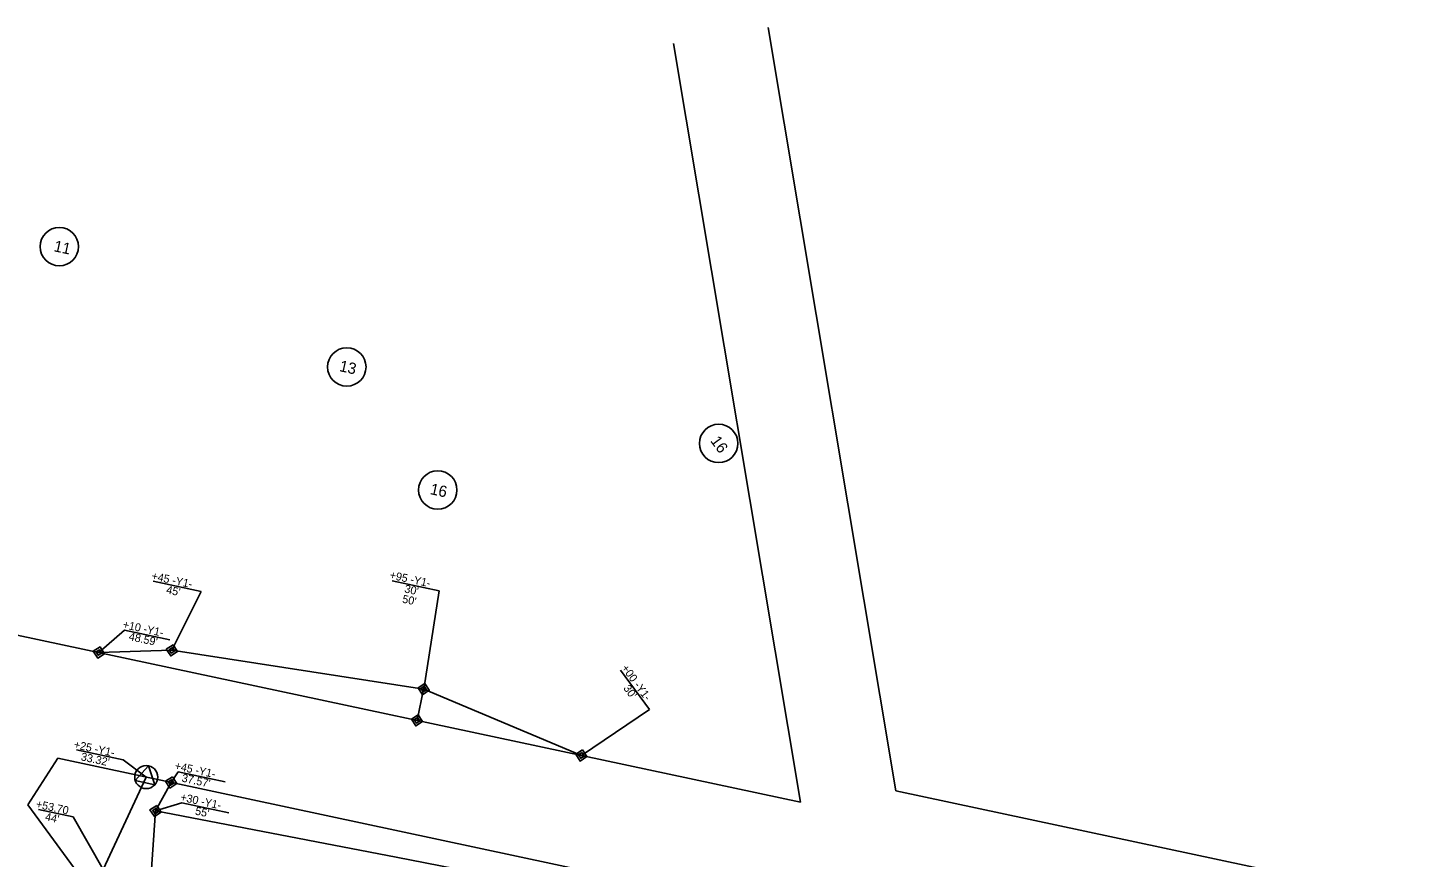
# Model space of a CAD drawing. Extents: x 1762160 to 1765875, y 710174 to 712931.
# Drawn here: x 1763351 to 1764211, y 712412 to 712931 of the extents above; entities that cross this region are included whole.
import ezdxf

# ---------------------------------------------------------------- set-up
doc = ezdxf.new("R2010")
doc.units = 0
for name, color, linetype in [('Exist Building Foundations', 7, 'Continuous'), ('Exist Other Culture Area Outline', 7, 'Continuous'), ('Exist Other Culture Fence Line', 7, 'Continuous'), ('Exist Other Culture Sign CELL', 7, 'Continuous'), ('Exist Roads Curbs', 7, 'Continuous'), ('Exist Roads EOP Other', 7, 'Continuous'), ('Exist Roads Soil', 7, 'Continuous'), ('Exist Structure Minor Head and End Wall', 7, 'Continuous'), ('Exist Utilities Other Pole CELL', 7, 'Continuous'), ('Exist Utilities Other Pole With Base CELL', 7, 'Continuous'), ('Exist Vegetation Tree CELL', 7, 'Continuous'), ('Exist Vegetation Woods Line', 7, 'Continuous')]:
    doc.layers.add(name, color=color, linetype=linetype)

msp = doc.modelspace()

# ---------------------------------------------------------------- linework, layer by layer
at = {"layer": 'Exist Building Foundations'}
for p, q in [((1763598.19, 712517.51), (1763696.71, 712476.04)), ((1763430.66, 712441.3), (1763440.39, 712459.14)), ((1763430.66, 712441.3), (1763425.35, 712367.49))]:
    msp.add_line(p, q, dxfattribs=at)
at = {"layer": 'Exist Other Culture Area Outline'}
msp.add_line((1763397.92, 712404.8), (1763424.78, 712462.47), dxfattribs=at)
at = {"layer": 'Exist Other Culture Fence Line'}
for p, q in [((1763721.2, 712529.24), (1763739.21, 712504.73)), ((1763739.21, 712504.73), (1763696.71, 712476.04)), ((1763440.39, 712459.14), (1763444.76, 712465.75)), ((1763444.76, 712465.75), (1763474.16, 712459.43)), ((1763447.12, 712446.4), (1763430.66, 712441.3)), ((1763447.12, 712446.4), (1763476.51, 712440.08))]:
    msp.add_line(p, q, dxfattribs=at)
at = {"layer": 'Exist Other Culture Sign CELL'}
for p, q in [((1763459.18, 712578.43), (1763429.19, 712584.88)), ((1763607.79, 712578.88), (1763578.48, 712585.18)), ((1763459.18, 712578.43), (1763440.86, 712541.72)), ((1763607.79, 712578.88), (1763598.19, 712517.51)), ((1763411.32, 712554.41), (1763395.21, 712540.36)), ((1763439.57, 712548.33), (1763411.32, 712554.41))]:
    msp.add_line(p, q, dxfattribs=at)
at = {"layer": 'Exist Roads Curbs'}
for p, q in [((1763395.21, 712540.36), (1763395.21, 712540.36)), ((1763440.86, 712541.72), (1763440.86, 712541.72)), ((1763598.19, 712517.51), (1763598.19, 712517.51)), ((1763594.02, 712497.95), (1763594.02, 712497.95)), ((1763696.71, 712476.04), (1763696.71, 712476.04)), ((1763424.78, 712462.47), (1763424.78, 712462.47)), ((1763440.39, 712459.14), (1763440.39, 712459.14)), ((1763430.66, 712441.3), (1763430.66, 712441.3))]:
    msp.add_line(p, q, dxfattribs=at)
msp.add_lwpolyline([(1763417.91, 712460.27), (1763426.3, 712469.51), (1763430.14, 712457.64)], close=True, dxfattribs=at)
msp.add_circle((1763424.78, 712462.47), 7.2, dxfattribs=at)
at = {"layer": 'Exist Roads EOP Other'}
for p, q in [((1763430.66, 712441.3), (1763580.9, 712412.49)), ((1763580.9, 712412.49), (1763654.53, 712398.13))]:
    msp.add_line(p, q, dxfattribs=at)
at = {"layer": 'Exist Roads Soil'}
for p, q in [((1763395.21, 712540.36), (1763440.86, 712541.72)), ((1763440.86, 712541.72), (1763598.19, 712517.51)), ((1763594.02, 712497.95), (1763598.12, 712517.52))]:
    msp.add_line(p, q, dxfattribs=at)
at = {"layer": 'Exist Structure Minor Head and End Wall'}
for points in [[(1763391.69, 712541.11), (1763395.96, 712543.87), (1763398.72, 712539.6), (1763394.45, 712536.84)], [(1763393.45, 712540.73), (1763395.58, 712542.11), (1763396.97, 712539.98), (1763394.83, 712538.6)], [(1763437.34, 712542.47), (1763441.62, 712545.23), (1763444.38, 712540.96), (1763440.11, 712538.2)], [(1763439.1, 712542.09), (1763441.24, 712543.47), (1763442.62, 712541.34), (1763440.48, 712539.96)], [(1763598.96, 712521.02), (1763601.71, 712516.74), (1763597.43, 712513.99), (1763594.67, 712518.27)], [(1763598.57, 712519.27), (1763599.95, 712517.12), (1763597.81, 712515.75), (1763596.43, 712517.89)], [(1763594.78, 712501.46), (1763597.54, 712497.18), (1763593.26, 712494.43), (1763590.5, 712498.71)], [(1763594.4, 712499.71), (1763595.78, 712497.56), (1763593.64, 712496.19), (1763592.26, 712498.33)], [(1763697.47, 712479.56), (1763700.23, 712475.28), (1763695.95, 712472.53), (1763693.19, 712476.81)], [(1763697.09, 712477.8), (1763698.47, 712475.66), (1763696.33, 712474.28), (1763694.95, 712476.42)], [(1763441.16, 712462.66), (1763443.91, 712458.38), (1763439.63, 712455.62), (1763436.87, 712459.91)], [(1763440.77, 712460.9), (1763442.15, 712458.76), (1763440.01, 712457.38), (1763438.63, 712459.52)], [(1763431.43, 712444.82), (1763434.18, 712440.54), (1763429.9, 712437.78), (1763427.14, 712442.07)], [(1763431.04, 712443.06), (1763432.42, 712440.92), (1763430.28, 712439.54), (1763428.9, 712441.68)]]:
    msp.add_lwpolyline(points, close=True, dxfattribs=at)
at = {"layer": 'Exist Utilities Other Pole CELL'}
for p, q in [((1763410.41, 712473.24), (1763381.12, 712479.54)), ((1763379.24, 712437.55), (1763357.41, 712442.25)), ((1763379.24, 712437.55), (1763397.92, 712404.8))]:
    msp.add_line(p, q, dxfattribs=at)
msp.add_lwpolyline([(1763410.41, 712473.24), (1763424.78, 712462.47)], dxfattribs=at)
at = {"layer": 'Exist Utilities Other Pole With Base CELL'}
for p, q in [((1763813.51, 712931), (1763893.25, 712453.96)), ((1763754.33, 712921.11), (1763833.61, 712446.84)), ((1763172.39, 712587.88), (1763833.61, 712446.84)), ((1763369.65, 712474.23), (1763350.79, 712445.09)), ((1763369.65, 712474.23), (1763839.56, 712374)), ((1763893.25, 712453.96), (1764211.09, 712386.16)), ((1763977.6, 711592.75), (1763350.79, 712445.09))]:
    msp.add_line(p, q, dxfattribs=at)
at = {"layer": 'Exist Vegetation Tree CELL'}
for centre in [(1763370.47, 712794.06), (1763550.14, 712718.84), (1763782.54, 712671.03), (1763606.99, 712641.92)]:
    msp.add_circle(centre, 12, dxfattribs=at)

# ---------------------------------------------------------------- texts
at = {"layer": 'Exist Other Culture Fence Line'}
for s, rotation, p in [('+00 -Y1-', 306.30835, (1763721.51, 712530.57)), ("30'", 306.30835, (1763722.7, 712517.97)), ('+45 -Y1-', 347.86389, (1763442.25, 712467.33)), ("37.57'", 347.86389, (1763446.66, 712459.73)), ('+30 -Y1-', 347.86389, (1763445.8, 712447.75)), ("55'", 347.86389, (1763455.04, 712439.11))]:
    msp.add_text(s, height=5, rotation=rotation, dxfattribs=at).set_placement(p)
at = {"layer": 'Exist Other Culture Sign CELL'}
for s, p in [('+45 -Y1-', (1763427.77, 712586.02)), ('+95 -Y1-', (1763576.59, 712586.59)), ("45'", (1763437.01, 712577.38)), ("30'", (1763585.84, 712577.95)), ("50'", (1763584.47, 712571.6)), ('+10 -Y1-', (1763409.79, 712555.66)), ("48.59'", (1763413.61, 712548.19))]:
    msp.add_text(s, height=5, rotation=347.86389, dxfattribs=at).set_placement(p)
at = {"layer": 'Exist Utilities Other Pole CELL'}
for s, p in [('+25 -Y1-', (1763379.22, 712480.62)), ("33.32'", (1763383.63, 712473.02)), ('+53.70', (1763355.55, 712443.39)), ("44'", (1763361.25, 712435.51))]:
    msp.add_text(s, height=5, rotation=347.86389, dxfattribs=at).set_placement(p)
at = {"layer": 'Exist Vegetation Woods Line'}
for s, rotation, p in [('11', 347.86389, (1763366.62, 712791.25)), ('13', 347.86389, (1763545.09, 712716.3)), ('16', 306.30835, (1763777.05, 712672.62)), ('16', 347.86389, (1763601.8, 712639.41))]:
    msp.add_text(s, height=7, rotation=rotation, dxfattribs=at).set_placement(p)

doc.saveas('drawing.dxf')
